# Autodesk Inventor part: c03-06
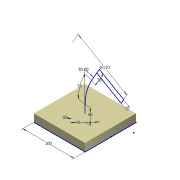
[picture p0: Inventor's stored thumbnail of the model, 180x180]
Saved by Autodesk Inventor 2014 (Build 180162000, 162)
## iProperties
Created: 2011-11
Part Number: c03-06
Material: Iron, Cast
Document SubType Name: Modeling
Designer: Thom Tremblay
Density: 7.25 g/cm^3
Mass: 1087.5 g
Surface Area: 260 cm^2
Volume: 150 cm^3
Appearance: Nylon 6
Author: Thom Tremblay
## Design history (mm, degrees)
sketch "Sketch1"
  geometry: L1 (50, -50)-(-50, -50); L2 (-50, -50)-(-50, 50); L3 (-50, 50)-(50, 50); L4 (50, 50)-(50, -50); C1 r 20 at (0, 0); C2 r 30 at (0, 0); 3 further points
  constraints: 8 end point, 2 centre point, 2 coincident, 2 midpoint, 2 parallel, 2 perpendicular, 1 horizontal, 1 horizontal alignment, 1 vertical alignment
  dimensions: "d0" = 100 distance of L2.end L3.end; "d3" = 40 diameter of C1; "d4" = 10 radial gap between concentric circles of C2 C1
extrude "Extrusion1" new body sketch "Sketch1" distance "d1" = 15; taper "d2" = 0 deg
sketch "Sketch2"
  geometry: L1 (0, 0)-(0, 30); L2 (12.794, 77.746)-(27.794, 103.727); A1 r 95.493 centre (95.493, 30) between (12.794, 77.746) and (0, 30)
  constraints: 4 end point, 2 point on circle, 2 tangent, 1 centre point, 1 vertical
  dimensions: "d5" = 30 distance of L1.start L1.end; "d7" = 50 dimension on A1; "d9" = 30 distance of L2.start L2.end; "d10" = 30 deg angle of L2 L1
sketch "Sketch3"
  geometry: L1 (12.794, 77.746)-(27.794, 103.727) reference; L2 (27.794, 103.727)-(75.425, 76.227); L3 (75.425, 76.227)-(70.425, 67.567); L4 (70.425, 67.567)-(22.794, 95.067); L5 (22.794, 95.067)-(27.794, 103.727); 1 further point
  constraints: 8 end point, 2 parallel, 2 perpendicular
  dimensions: "d11" = 110 diameter of L3 L5; "d13" = 10 distance between parallel lines of L2 L4
body "Solid1"
